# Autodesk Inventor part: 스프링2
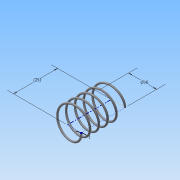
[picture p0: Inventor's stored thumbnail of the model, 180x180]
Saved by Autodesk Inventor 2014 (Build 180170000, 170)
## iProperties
Created: 2015-06
Part Number: 스프링2
Material: 강철, 연강
Document SubType Name: Modeling
Designer: Administrator
Density: 7.86 g/cm^3
Appearance: 강철
Mass: 1.52988 g
Surface Area: 7.87024 cm^2
Volume: 0.194641 cm^3
Author: Administrator
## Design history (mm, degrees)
sketch "스케치1"
  geometry: L1 (0, 0)-(8, 0); L2 (8, 0)-(8, 14.5); L3 (8, 14.5)-(0, 14.5); L4 (0, 14.5)-(0, 0); C1 r 0.5 at (8, 0)
  constraints: 8 end point, 2 parallel, 1 centre point, 1 coincident, 1 horizontal, 1 perpendicular
  dimensions: "d0" = 14.5 distance of L3.end L1.start (derived); "d1" = 16 diameter of L2 L4; "d2" = 1 diameter of C1
feature "코일1" sketch "스케치1" pitch "d3" = 10; turns "d5" = 5; dims "d4" = 14.5 (= d0), "d6" = 0, angle "d7" = 90 deg, angle "d8" = 90 deg, "d9" = 0, "d10" = 0
sketch "스케치2"
  geometry: L1 (-8.5, 0)-(-7.5, 0) reference; 1 further point
  constraints: 1 horizontal alignment
extrude "돌출1" cut sketch "스케치2" distance "d11" = 10; taper "d12" = 0 deg
node "작업 평면1"
sketch "스케치3"
  geometry: L1 (-7.5, 0)-(-8.5, 0) reference; 1 further point
  constraints: 1 horizontal alignment
extrude "돌출2" cut sketch "스케치3" distance "d14" = 10; taper "d15" = 0 deg
node "솔리드1"
node "절단 모서리 투영1"
node "절단 모서리 투영2"
other parameters: "d13" = 14.5 (= d0)
